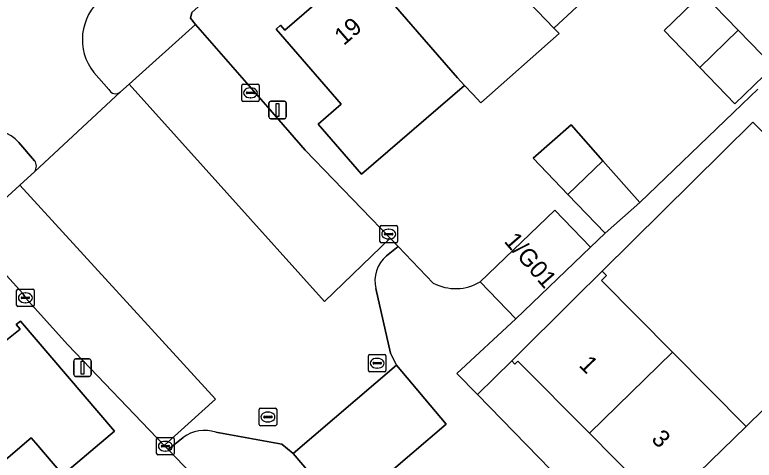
# Model space of a CAD drawing. Extents: x 157445 to 158888, y 383061 to 384688.
# Drawn here: x 158011.77 to 158054.19, y 383656.98 to 383682.54 of the extents above; entities that cross this region are included whole.
import ezdxf

# ---------------------------------------------------------------- set-up
doc = ezdxf.new("R2010")
doc.units = 0
for name, color, linetype in [('IMGEO_Erf', 7, 'Continuous'), ('IMGEO_Kolk', 7, 'Continuous'), ('IMGEO_Lichtmast', 7, 'Continuous'), ('IMGEO_Pand', 7, 'Continuous'), ('IMGEO_Pand_nummerreeks', 7, 'Continuous'), ('IMGEO_Parkeervlak_open', 7, 'Continuous'), ('IMGEO_Rijbaan_lokaal_open', 7, 'Continuous'), ('IMGEO_Rioolput', 7, 'Continuous'), ('IMGEO_Voetpad_open', 7, 'Continuous')]:
    doc.layers.add(name, color=color, linetype=linetype)

msp = doc.modelspace()

# ---------------------------------------------------------------- linework, layer by layer
at = {"layer": 'IMGEO_Erf'}
for points in [[(158047.152, 383685.93), (158042.69, 383681.771), (158042.999, 383681.46), (158038.509, 383677.491), (158038.046, 383677.983), (158037.565, 383678.493), (158031.662, 383673.388), (158029.171, 383676.269), (158030.495, 383677.414), (158026.766, 383681.725), (158027.02, 383681.945), (158027.267, 383681.66), (158031.569, 383685.38)], [(158021.919, 383682.679), (158021.849, 383682.357), (158022.137, 383681.981), (158026.297, 383677.24), (158028.432, 383674.777), (158033.301, 383669.722), (158033.765, 383669.24), (158035.779, 383667.149)], [(158038.475, 383667.221), (158042.755, 383671.327), (158044.792, 383669.205), (158045.63, 383670.016), (158043.5, 383672.232), (158041.506, 383674.307), (158043.69, 383676.229), (158045.509, 383674.162), (158047.618, 383671.765), (158052.992, 383676.931), (158053.948, 383677.856), (158054.386, 383678.28)], [(158056.476, 383673.999), (158054.116, 383676.385), (158045.464, 383667.826), (158045.71, 383667.578), (158045.427, 383667.298), (158049.497, 383663.186), (158053.719, 383658.92), (158055.759, 383660.913)], [(158022.792, 383655.277), (158020.569, 383657.597), (158020.339, 383657.837), (158014.816, 383663.599), (158012.381, 383666.302), (158012.232, 383666.546), (158009.061, 383670.029)], [(158010.633, 383663.362), (158012.09, 383664.505), (158011.854, 383664.762), (158012.101, 383664.966), (158017.498, 383658.647), (158014.531, 383656.155), (158012.982, 383657.958), (158012.714, 383658.27), (158008.303, 383654.494)], [(158057.312, 383645.815), (158053.12, 383650.05), (158048.951, 383654.263), (158044.729, 383658.528), (158040.633, 383662.667), (158040.465, 383662.5), (158040.276, 383662.692), (158038.32, 383660.756), (158062.095, 383636.318)]]:
    msp.add_lwpolyline(points, dxfattribs=at)
msp.add_lwpolyline([(158053.274, 383681.653), (158055.291, 383679.571), (158053.065, 383677.434), (158051.058, 383679.524), (158049.018, 383681.648), (158051.217, 383683.777)], close=True, dxfattribs=at)
msp.add_arc((158037.063, 383669.582), 2.751, 242.1817, 300.8779, dxfattribs=at)
at = {"layer": 'IMGEO_Kolk'}
for p, q in [((158024.794, 383677.639), (158024.794, 383678.491)), ((158024.869, 383678.565), (158025.721, 383678.565)), ((158025.282, 383678.345), (158025.307, 383678.345)), ((158025.795, 383678.491), (158025.795, 383677.639)), ((158025.053, 383678.059), (158025.053, 383678.071)), ((158025.491, 383678.022), (158025.093, 383678.022)), ((158025.096, 383678.108), (158025.494, 383678.108)), ((158025.305, 383677.785), (158025.28, 383677.785)), ((158025.537, 383678.071), (158025.537, 383678.059)), ((158025.721, 383677.565), (158024.869, 383677.565)), ((158032.72, 383669.532), (158032.72, 383670.384)), ((158032.795, 383670.458), (158033.647, 383670.458)), ((158033.208, 383670.238), (158033.233, 383670.238)), ((158033.721, 383670.384), (158033.721, 383669.532)), ((158032.979, 383669.952), (158032.979, 383669.964)), ((158033.417, 383669.915), (158033.019, 383669.915)), ((158033.022, 383670.001), (158033.42, 383670.001)), ((158033.463, 383669.964), (158033.463, 383669.952)), ((158033.647, 383669.458), (158032.795, 383669.458)), ((158033.231, 383669.678), (158033.206, 383669.678)), ((158011.955, 383666.803), (158012.807, 383666.803)), ((158011.88, 383665.877), (158011.88, 383666.729)), ((158012.182, 383666.346), (158012.58, 383666.346)), ((158012.368, 383666.583), (158012.393, 383666.583)), ((158012.881, 383666.729), (158012.881, 383665.877)), ((158012.139, 383666.297), (158012.139, 383666.309)), ((158012.577, 383666.26), (158012.179, 383666.26)), ((158012.391, 383666.023), (158012.366, 383666.023)), ((158012.623, 383666.309), (158012.623, 383666.297)), ((158012.807, 383665.803), (158011.955, 383665.803)), ((158019.983, 383658.287), (158020.835, 383658.287)), ((158019.908, 383657.361), (158019.908, 383658.213)), ((158020.396, 383658.067), (158020.421, 383658.067)), ((158020.909, 383658.213), (158020.909, 383657.361)), ((158020.167, 383657.781), (158020.167, 383657.793)), ((158020.605, 383657.744), (158020.207, 383657.744)), ((158020.21, 383657.83), (158020.608, 383657.83)), ((158020.419, 383657.507), (158020.394, 383657.507)), ((158020.651, 383657.793), (158020.651, 383657.781)), ((158020.835, 383657.287), (158019.983, 383657.287))]:
    msp.add_line(p, q, dxfattribs=at)
for points in [[(158024.794, 383677.639), (158024.794, 383678.491)], [(158024.869, 383678.565), (158025.721, 383678.565)], [(158025.795, 383678.491), (158025.795, 383677.639)], [(158025.721, 383677.565), (158024.869, 383677.565)], [(158032.72, 383669.532), (158032.72, 383670.384)], [(158032.795, 383670.458), (158033.647, 383670.458)], [(158033.721, 383670.384), (158033.721, 383669.532)], [(158033.647, 383669.458), (158032.795, 383669.458)], [(158011.955, 383666.803), (158012.807, 383666.803)], [(158011.88, 383665.877), (158011.88, 383666.729)], [(158012.881, 383666.729), (158012.881, 383665.877)], [(158012.807, 383665.803), (158011.955, 383665.803)], [(158019.983, 383658.287), (158020.835, 383658.287)], [(158019.908, 383657.361), (158019.908, 383658.213)], [(158020.909, 383658.213), (158020.909, 383657.361)], [(158020.835, 383657.287), (158019.983, 383657.287)]]:
    msp.add_lwpolyline(points, dxfattribs=at)
for centre, radius, start, end in [((158024.871, 383678.489), 0.0765, 91.552, 178.448), ((158024.871, 383678.489), 0.0765, 91.552, 178.448), ((158025.719, 383678.489), 0.0765, 1.552, 88.448), ((158025.719, 383678.489), 0.0765, 1.552, 88.448), ((158025.093, 383678.068), 0.0403, 85.8775, 175.7526), ((158025.09, 383678.058), 0.0366, 178.938, 274.7102), ((158025.494, 383678.065), 0.043, 264.8664, 352.4533), ((158025.498, 383678.07), 0.0386, 1.7309, 96.639), ((158024.871, 383677.641), 0.0765, 181.552, 268.448), ((158024.871, 383677.641), 0.0765, 181.552, 268.448), ((158025.719, 383677.641), 0.0765, 271.552, 358.448), ((158025.719, 383677.641), 0.0765, 271.552, 358.448), ((158032.797, 383670.382), 0.0765, 91.552, 178.448), ((158032.797, 383670.382), 0.0765, 91.552, 178.448), ((158033.645, 383670.382), 0.0765, 1.552, 88.448), ((158033.645, 383670.382), 0.0765, 1.552, 88.448), ((158033.019, 383669.961), 0.0403, 85.8775, 175.7526), ((158033.016, 383669.951), 0.0366, 178.938, 274.7102), ((158033.42, 383669.958), 0.043, 264.8664, 352.4533), ((158033.424, 383669.963), 0.0386, 1.7309, 96.639), ((158032.797, 383669.534), 0.0765, 181.552, 268.448), ((158032.797, 383669.534), 0.0765, 181.552, 268.448), ((158033.645, 383669.534), 0.0765, 271.552, 358.448), ((158033.645, 383669.534), 0.0765, 271.552, 358.448), ((158011.957, 383666.727), 0.0765, 91.552, 178.448), ((158011.957, 383666.727), 0.0765, 91.552, 178.448), ((158012.805, 383666.727), 0.0765, 1.552, 88.448), ((158012.805, 383666.727), 0.0765, 1.552, 88.448), ((158012.179, 383666.306), 0.0403, 85.8775, 175.7526), ((158012.584, 383666.308), 0.0386, 1.7309, 96.639), ((158012.176, 383666.296), 0.0366, 178.938, 274.7102), ((158012.58, 383666.303), 0.043, 264.8664, 352.4533), ((158011.957, 383665.879), 0.0765, 181.552, 268.448), ((158011.957, 383665.879), 0.0765, 181.552, 268.448), ((158012.805, 383665.879), 0.0765, 271.552, 358.448), ((158012.805, 383665.879), 0.0765, 271.552, 358.448), ((158019.985, 383658.211), 0.0765, 91.552, 178.448), ((158019.985, 383658.211), 0.0765, 91.552, 178.448), ((158020.833, 383658.211), 0.0765, 1.552, 88.448), ((158020.833, 383658.211), 0.0765, 1.552, 88.448), ((158020.207, 383657.79), 0.0403, 85.8775, 175.7526), ((158020.204, 383657.78), 0.0366, 178.938, 274.7102), ((158020.608, 383657.787), 0.043, 264.8664, 352.4533), ((158020.612, 383657.792), 0.0386, 1.7309, 96.639), ((158019.985, 383657.363), 0.0765, 181.552, 268.448), ((158019.985, 383657.363), 0.0765, 181.552, 268.448), ((158020.833, 383657.363), 0.0765, 271.552, 358.448), ((158020.833, 383657.363), 0.0765, 271.552, 358.448)]:
    msp.add_arc(centre, radius, start, end, dxfattribs=at)
for centre, major_axis, ratio, start_param, end_param in [((158025.281, 383678.065), (-0.387, 0.002), 0.722429, 4.712389, 7.853982), ((158025.306, 383678.065), (-0.39, 0.002), 0.717154, 1.570796, 4.712389), ((158033.207, 383669.958), (-0.387, 0.002), 0.722429, 4.712389, 7.853982), ((158033.232, 383669.958), (-0.39, 0.002), 0.717154, 1.570796, 4.712389), ((158012.367, 383666.303), (-0.387, 0.002), 0.722429, 4.712389, 7.853982), ((158012.392, 383666.303), (-0.39, 0.002), 0.717154, 1.570796, 4.712389), ((158020.395, 383657.787), (-0.387, 0.002), 0.722429, 4.712389, 7.853982), ((158020.42, 383657.787), (-0.39, 0.002), 0.717154, 1.570796, 4.712389)]:
    msp.add_ellipse(centre, major_axis=major_axis, ratio=ratio, start_param=start_param, end_param=end_param, dxfattribs=at)
at = {"layer": 'IMGEO_Lichtmast'}
for p, q in [((158026.351, 383676.681), (158026.351, 383677.481)), ((158026.351, 383677.481), (158026.351, 383676.681)), ((158026.451, 383677.581), (158027.241, 383677.581)), ((158027.241, 383677.581), (158026.451, 383677.581)), ((158027.341, 383677.481), (158027.341, 383676.681)), ((158027.341, 383676.681), (158027.341, 383677.481)), ((158027.241, 383676.581), (158026.451, 383676.581)), ((158026.451, 383676.581), (158027.241, 383676.581)), ((158015.155, 383661.895), (158015.155, 383662.695)), ((158015.155, 383662.695), (158015.155, 383661.895)), ((158015.255, 383662.795), (158016.045, 383662.795)), ((158016.045, 383662.795), (158015.255, 383662.795)), ((158016.145, 383662.695), (158016.145, 383661.895)), ((158016.145, 383661.895), (158016.145, 383662.695)), ((158016.045, 383661.795), (158015.255, 383661.795)), ((158015.255, 383661.795), (158016.045, 383661.795))]:
    msp.add_line(p, q, dxfattribs=at)
for points in [[(158026.771, 383677.456), (158026.921, 383677.456), (158026.921, 383676.706), (158026.771, 383676.706), (158026.771, 383677.456)], [(158015.575, 383662.67), (158015.725, 383662.67), (158015.725, 383661.92), (158015.575, 383661.92), (158015.575, 383662.67)]]:
    msp.add_lwpolyline(points, dxfattribs=at)
for centre, start, end in [((158026.451, 383677.481), 90, 180), ((158026.451, 383677.481), 90, 180), ((158027.241, 383677.481), 0, 90), ((158027.241, 383677.481), 360, 90), ((158026.451, 383676.681), 180, 270), ((158026.451, 383676.681), 180, 270), ((158027.241, 383676.681), 270, 0), ((158027.241, 383676.681), 270, 0), ((158015.255, 383662.695), 90, 180), ((158015.255, 383662.695), 90, 180), ((158016.045, 383662.695), 0, 90), ((158016.045, 383662.695), 360, 90), ((158015.255, 383661.895), 180, 270), ((158015.255, 383661.895), 180, 270), ((158016.045, 383661.895), 270, 0), ((158016.045, 383661.895), 270, 0)]:
    msp.add_arc(centre, 0.1, start, end, dxfattribs=at)
at = {"layer": 'IMGEO_Pand'}
for points in [[(158040.682, 383693.261), (158036.047, 383689.253), (158040.806, 383683.758), (158042.69, 383681.771), (158047.152, 383685.93), (158045.44, 383687.766)], [(158040.806, 383683.758), (158036.047, 383689.253), (158031.569, 383685.38), (158037.168, 383678.915), (158037.565, 383678.493), (158038.046, 383677.983), (158038.509, 383677.491), (158042.999, 383681.46), (158042.69, 383681.771)], [(158031.569, 383685.38), (158027.267, 383681.66), (158027.02, 383681.945), (158026.766, 383681.725), (158030.495, 383677.414), (158029.171, 383676.269), (158031.662, 383673.388), (158037.565, 383678.493), (158037.168, 383678.915)], [(158053.274, 383681.653), (158051.217, 383683.777), (158049.018, 383681.648), (158051.058, 383679.524)], [(158053.274, 383681.653), (158051.058, 383679.524), (158053.065, 383677.434), (158055.291, 383679.571)], [(158043.69, 383676.229), (158041.506, 383674.307), (158043.5, 383672.232), (158045.509, 383674.162)], [(158045.509, 383674.162), (158043.5, 383672.232), (158045.63, 383670.016), (158047.618, 383671.765)], [(158038.475, 383667.221), (158040.512, 383665.098), (158044.792, 383669.205), (158042.755, 383671.327)], [(158049.497, 383663.186), (158045.427, 383667.298), (158045.71, 383667.578), (158045.464, 383667.826), (158043.876, 383666.255), (158040.276, 383662.692), (158040.465, 383662.5), (158040.633, 383662.667), (158044.729, 383658.528)], [(158008.303, 383654.494), (158012.714, 383658.27), (158012.982, 383657.958), (158014.531, 383656.155), (158017.498, 383658.647), (158012.101, 383664.966), (158011.854, 383664.762), (158012.09, 383664.505), (158010.633, 383663.362), (158009.559, 383662.338), (158008.353, 383663.735), (158008.105, 383663.584), (158008.317, 383663.337), (158003.932, 383659.572)], [(158049.497, 383663.186), (158044.729, 383658.528), (158048.951, 383654.263), (158053.719, 383658.92)], [(158053.12, 383650.05), (158057.888, 383654.708), (158059.947, 383656.682), (158055.759, 383660.913), (158053.719, 383658.92), (158048.951, 383654.263)]]:
    msp.add_lwpolyline(points, close=True, dxfattribs=at)
at = {"layer": 'IMGEO_Parkeervlak_open'}
for points in [[(158028.432, 383674.777), (158026.297, 383677.24), (158022.137, 383681.981), (158018.338, 383678.57), (158029.537, 383666.096), (158033.301, 383669.722)], [(158012.059, 383672.767), (158009.061, 383670.029), (158012.232, 383666.546), (158012.381, 383666.302), (158014.816, 383663.599), (158020.339, 383657.837), (158023.282, 383660.48)], [(158027.75, 383657.373), (158030.605, 383654.01), (158036.509, 383659.061), (158033.669, 383662.438)]]:
    msp.add_lwpolyline(points, close=True, dxfattribs=at)
at = {"layer": 'IMGEO_Rijbaan_lokaal_open'}
for points in [[(158017.167, 383678.253), (158016.305, 383679.228)], [(158018.338, 383678.57), (158017.829, 383678.113), (158012.919, 383673.553), (158012.059, 383672.767), (158023.282, 383660.48), (158020.339, 383657.837), (158020.569, 383657.597), (158021.424, 383658.284)], [(158033.091, 383668.717), (158033.765, 383669.24), (158033.301, 383669.722), (158029.537, 383666.096), (158018.338, 383678.57)], [(158012.919, 383673.553), (158017.829, 383678.113)], [(158012.009, 383675.219), (158012.91, 383674.169)], [(158035.779, 383667.149), (158033.765, 383669.24), (158033.091, 383668.717)], [(158038.32, 383660.756), (158037.131, 383661.964), (158040.512, 383665.098), (158038.475, 383667.221)], [(158032.477, 383666.829), (158033.315, 383663.131), (158033.669, 383662.438), (158036.509, 383659.061), (158030.605, 383654.01), (158027.75, 383657.373), (158027.089, 383657.911), (158023.307, 383658.59)], [(158023.307, 383658.59), (158027.089, 383657.911), (158027.75, 383657.373), (158033.669, 383662.438), (158033.315, 383663.131), (158032.477, 383666.829)], [(158062.095, 383636.318), (158038.32, 383660.756)], [(158021.424, 383658.284), (158020.569, 383657.597), (158022.792, 383655.277)]]:
    msp.add_lwpolyline(points, dxfattribs=at)
for centre, radius, start, end in [((158018.689, 383681.116), 3.041, 129.2263, 218.372), ((158017.551, 383678.435), 0.425, 205.3272, 310.7908), ((158009.964, 383673.189), 2.881, 44.801, 134.6074), ((158012.471, 383673.855), 0.54, 326.0463, 35.6278), ((158034.375, 383667.255), 1.946, 131.3077, 192.662), ((158034.375, 383667.255), 1.946, 131.3077, 192.662), ((158037.063, 383669.582), 2.751, 242.1817, 300.8779), ((158022.666, 383656.589), 2.102, 72.2383, 126.2222), ((158022.666, 383656.589), 2.102, 72.2383, 126.2222)]:
    msp.add_arc(centre, radius, start, end, dxfattribs=at)
at = {"layer": 'IMGEO_Rioolput'}
for p, q in [((158032.061, 383662.124), (158032.061, 383662.976)), ((158032.136, 383663.05), (158032.988, 383663.05)), ((158033.062, 383662.976), (158033.062, 383662.124)), ((158032.32, 383662.544), (158032.32, 383662.556)), ((158032.758, 383662.507), (158032.36, 383662.507)), ((158032.363, 383662.593), (158032.761, 383662.593)), ((158032.549, 383662.83), (158032.574, 383662.83)), ((158032.804, 383662.556), (158032.804, 383662.544)), ((158032.572, 383662.27), (158032.547, 383662.27)), ((158032.988, 383662.05), (158032.136, 383662.05)), ((158025.869, 383659.965), (158026.721, 383659.965)), ((158025.794, 383659.039), (158025.794, 383659.891)), ((158026.282, 383659.745), (158026.307, 383659.745)), ((158026.795, 383659.891), (158026.795, 383659.039)), ((158026.053, 383659.459), (158026.053, 383659.471)), ((158026.491, 383659.422), (158026.093, 383659.422)), ((158026.096, 383659.508), (158026.494, 383659.508)), ((158026.305, 383659.185), (158026.28, 383659.185)), ((158026.537, 383659.471), (158026.537, 383659.459)), ((158026.721, 383658.965), (158025.869, 383658.965))]:
    msp.add_line(p, q, dxfattribs=at)
for points in [[(158032.061, 383662.124), (158032.061, 383662.976)], [(158032.136, 383663.05), (158032.988, 383663.05)], [(158033.062, 383662.976), (158033.062, 383662.124)], [(158032.988, 383662.05), (158032.136, 383662.05)], [(158025.869, 383659.965), (158026.721, 383659.965)], [(158025.794, 383659.039), (158025.794, 383659.891)], [(158026.795, 383659.891), (158026.795, 383659.039)], [(158026.721, 383658.965), (158025.869, 383658.965)]]:
    msp.add_lwpolyline(points, dxfattribs=at)
for centre, radius, start, end in [((158032.138, 383662.974), 0.0765, 91.552, 178.448), ((158032.138, 383662.974), 0.0765, 91.552, 178.448), ((158032.986, 383662.974), 0.0765, 1.552, 88.448), ((158032.986, 383662.974), 0.0765, 1.552, 88.448), ((158032.36, 383662.553), 0.0403, 85.8775, 175.7526), ((158032.357, 383662.543), 0.0366, 178.938, 274.7102), ((158032.761, 383662.55), 0.043, 264.8664, 352.4533), ((158032.765, 383662.555), 0.0386, 1.7309, 96.639), ((158032.138, 383662.126), 0.0765, 181.552, 268.448), ((158032.138, 383662.126), 0.0765, 181.552, 268.448), ((158032.986, 383662.126), 0.0765, 271.552, 358.448), ((158032.986, 383662.126), 0.0765, 271.552, 358.448), ((158025.871, 383659.889), 0.0765, 91.552, 178.448), ((158025.871, 383659.889), 0.0765, 91.552, 178.448), ((158026.719, 383659.889), 0.0765, 1.552, 88.448), ((158026.719, 383659.889), 0.0765, 1.552, 88.448), ((158026.093, 383659.468), 0.0403, 85.8775, 175.7526), ((158026.09, 383659.458), 0.0366, 178.938, 274.7102), ((158026.494, 383659.465), 0.043, 264.8664, 352.4533), ((158026.498, 383659.47), 0.0386, 1.7309, 96.639), ((158025.871, 383659.041), 0.0765, 181.552, 268.448), ((158025.871, 383659.041), 0.0765, 181.552, 268.448), ((158026.719, 383659.041), 0.0765, 271.552, 358.448), ((158026.719, 383659.041), 0.0765, 271.552, 358.448)]:
    msp.add_arc(centre, radius, start, end, dxfattribs=at)
for centre, major_axis, ratio, start_param, end_param in [((158032.548, 383662.55), (-0.387, 0.002), 0.722429, 4.712389, 7.853982), ((158032.573, 383662.55), (-0.39, 0.002), 0.717154, 1.570796, 4.712389), ((158026.281, 383659.465), (-0.387, 0.002), 0.722429, 4.712389, 7.853982), ((158026.306, 383659.465), (-0.39, 0.002), 0.717154, 1.570796, 4.712389)]:
    msp.add_ellipse(centre, major_axis=major_axis, ratio=ratio, start_param=start_param, end_param=end_param, dxfattribs=at)
at = {"layer": 'IMGEO_Voetpad_open'}
for points in [[(158017.829, 383678.113), (158018.338, 383678.57), (158022.137, 383681.981), (158021.849, 383682.357), (158021.919, 383682.679), (158052.35, 383709.789)], [(158016.305, 383679.228), (158017.167, 383678.253)], [(158054.386, 383678.28), (158053.948, 383677.856), (158052.992, 383676.931), (158047.618, 383671.765), (158045.63, 383670.016), (158044.792, 383669.205), (158040.512, 383665.098), (158037.131, 383661.964), (158038.32, 383660.756), (158040.276, 383662.692), (158043.876, 383666.255), (158045.464, 383667.826), (158054.116, 383676.385), (158056.476, 383673.999)], [(158012.91, 383674.169), (158012.009, 383675.219)], [(158008.69, 383670.365), (158009.061, 383670.029), (158012.059, 383672.767), (158012.919, 383673.553)]]:
    msp.add_lwpolyline(points, dxfattribs=at)
for centre, radius, start, end in [((158018.689, 383681.116), 3.041, 129.2263, 218.372), ((158017.551, 383678.435), 0.425, 205.3272, 310.7908), ((158009.964, 383673.189), 2.881, 44.801, 134.6074), ((158012.471, 383673.855), 0.54, 326.0463, 35.6278)]:
    msp.add_arc(centre, radius, start, end, dxfattribs=at)

# ---------------------------------------------------------------- texts
at = {"layer": 'IMGEO_Pand_nummerreeks'}
for s, rotation, p in [('19', 40.892, (158030.643, 383680.744)), ('1/G01', 310.8151, (158039.797, 383669.524)), ('1', 314.328, (158044.083, 383662.4)), ('3', 314.328, (158048.238, 383658.147))]:
    msp.add_text(s, height=1, rotation=rotation, dxfattribs=at).set_placement(p)

doc.saveas('drawing.dxf')
